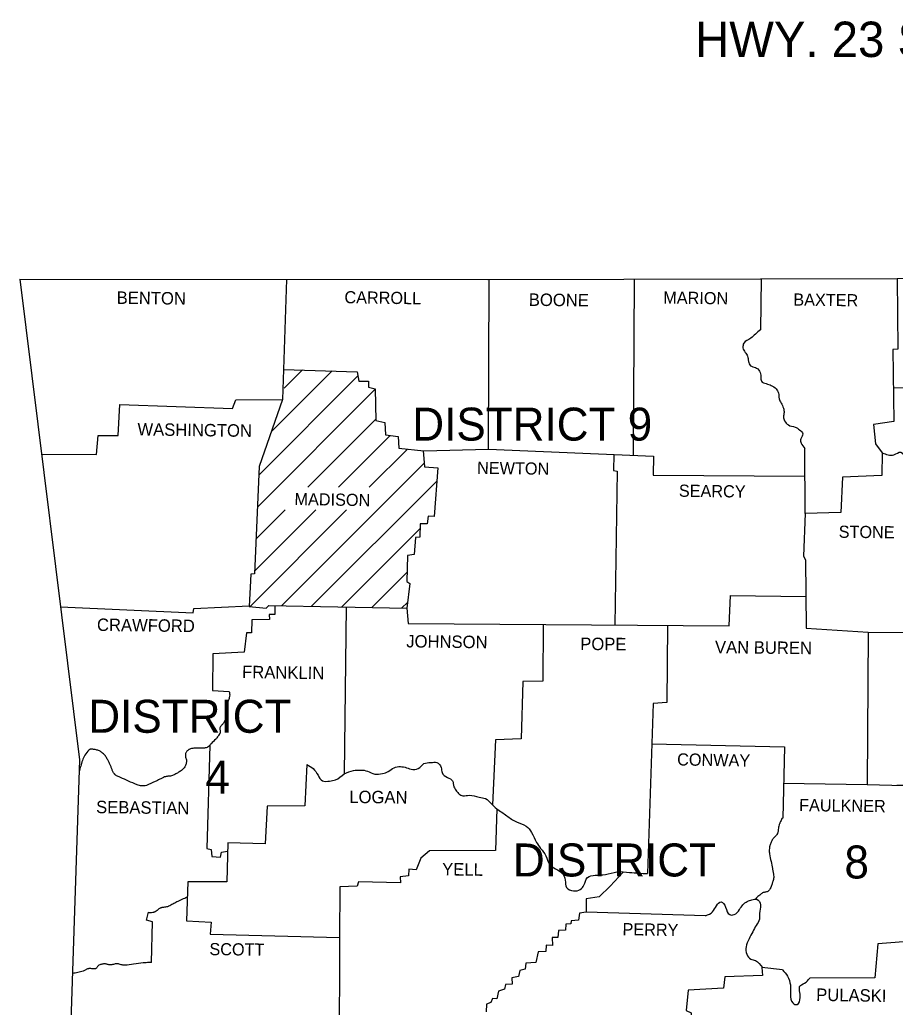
# Model space of a CAD drawing. Extents: x 0 to 3171, y 0 to 2059.
# Drawn here: x 2521.2 to 2824.1, y 1635.7 to 1977.1 of the extents above; entities that cross this region are included whole.
import ezdxf

# ---------------------------------------------------------------- set-up
doc = ezdxf.new("R2010")
doc.units = 0
doc.layers.add('Default', color=7, linetype='Continuous')
doc.layers.add('Level 1', color=7, linetype='Continuous')

msp = doc.modelspace()

# ---------------------------------------------------------------- linework, layer by layer
at = {"layer": 'Level 1'}
for p, q in [((2603.84, 1819.7), (2638.14, 1854)), ((2608.15, 1834.62), (2629.25, 1855.71)), ((2612.65, 1849.72), (2618.98, 1856.05)), ((2603.37, 1808.62), (2644.17, 1849.42)), ((2620.87, 1815.52), (2644.36, 1839.01)), ((2631.48, 1815.52), (2649.36, 1833.4)), ((2642.09, 1815.52), (2655.29, 1828.72)), ((2611.73, 1774.55), (2661.07, 1823.89)), ((2622.14, 1774.35), (2665.44, 1817.66)), ((2600.78, 1774.21), (2634.25, 1807.68)), ((2602.41, 1786.45), (2623.64, 1807.68)), ((2602.89, 1797.53), (2613.04, 1807.68)), ((2632.55, 1774.16), (2659.64, 1801.25)), ((2642.96, 1773.96), (2655.18, 1786.18)), ((2653.37, 1773.77), (2655.3, 1775.7))]:
    msp.add_line(p, q, dxfattribs=at)
for points in [[(2521.17, 1887.43), (2682.87, 1887.33), (2824.77, 1887.63), (2992.17, 1890.23), (3069.77, 1892.03)], [(2909.47, 1888.95), (2909.67, 1863.73), (2896.67, 1863.03), (2896.27, 1849.43), (2823.43, 1849.84)], [(2521.17, 1887.43), (2541.87, 1721.24), (2532.87, 1449.94)], [(2613.49, 1887.38), (2612.07, 1845.83)], [(2612.43, 1856.26), (2637.87, 1855.43), (2638.47, 1852.23), (2641.87, 1852.13), (2641.77, 1850.13), (2644.17, 1849.53), (2644.37, 1838.63), (2647.47, 1837.93), (2647.67, 1833.63), (2652.07, 1833.03), (2652.27, 1829.03), (2660.97, 1828.13), (2683.37, 1828.63), (2683.57, 1887.33)], [(2733.68, 1887.44), (2733.37, 1826.53)], [(2777.68, 1887.53), (2777.47, 1869.93)], [(2824.76, 1887.63), (2824.97, 1863.23), (2823.27, 1863.13), (2823.57, 1838.23), (2816.57, 1837.23), (2817.17, 1830.53), (2819.57, 1827.43), (2819.37, 1819.53), (2805.77, 1819.03), (2805.27, 1806.83), (2792.87, 1806.44), (2792.27, 1791.64), (2792.97, 1790.44), (2793.27, 1766.84), (2814.67, 1765.44), (2814.37, 1712.74), (2831.37, 1712.24), (2831.37, 1658.64), (2817.97, 1657.64), (2816.97, 1645.84), (2794.47, 1645.74)], [(2528.71, 1826.94), (2547.77, 1826.83), (2548.27, 1833.43), (2555.17, 1833.43), (2555.77, 1844.13), (2594.77, 1842.73), (2595.97, 1845.73), (2612.07, 1845.83), (2603.97, 1822.63), (2602.37, 1785.54), (2601.17, 1785.44), (2600.57, 1774.24), (2606.47, 1773.74), (2607.37, 1774.64), (2655.07, 1773.74), (2655.57, 1768.44)], [(2660.75, 1828.16), (2661.17, 1822.53), (2665.77, 1822.23), (2664.57, 1805.44), (2662.47, 1805.54), (2662.07, 1802.84), (2659.67, 1802.84), (2659.57, 1798.24), (2658.07, 1798.14), (2657.57, 1792.24), (2655.37, 1791.94), (2655.07, 1782.94), (2656.07, 1782.24), (2655.07, 1773.74)], [(2683.37, 1828.63), (2740.37, 1826.23), (2740.27, 1819.73), (2792.81, 1819.33)], [(2726.68, 1826.81), (2726.57, 1821.33), (2727.87, 1821.03), (2727.06, 1767.86)], [(2792.87, 1806.44), (2792.77, 1828.93)], [(2655.57, 1768.44), (2766.57, 1767.54), (2767.07, 1778.04), (2793.13, 1777.73)], [(2535.28, 1774.15), (2581.17, 1772.04), (2581.37, 1773.64), (2600.59, 1774.55)], [(2609.37, 1774.6), (2609.37, 1771.54), (2607.47, 1771.54), (2607.57, 1769.74), (2601.47, 1769.64), (2601.37, 1765.14), (2599.67, 1765.14), (2598.77, 1758.44), (2587.97, 1757.94), (2587.87, 1745.24), (2593.67, 1744.84)], [(2634.07, 1774.14), (2633.37, 1716.44)], [(2702.2, 1768.06), (2702.1, 1748.47), (2695.2, 1748.37), (2694.6, 1728.47), (2685.8, 1728.17), (2684.71, 1705.73)], [(2745.27, 1767.71), (2745.07, 1741.14), (2740.27, 1740.74), (2738.37, 1681.94)], [(2814.67, 1765.44), (2866.07, 1765.14), (2870.47, 1767.24), (2870.17, 1728.14), (2867.17, 1726.84), (2864.47, 1724.54), (2863.57, 1723.64), (2863.47, 1712.44), (2824.57, 1712.44)], [(2586.91, 1726.31), (2585.87, 1690.64), (2587.37, 1690.24), (2587.67, 1687.84), (2590.67, 1687.64), (2590.97, 1689.34), (2593.09, 1689.69)], [(2739.82, 1726.84), (2785.77, 1725.74), (2785.17, 1701.04)], [(2620.47, 1719.64), (2619.77, 1705.34), (2606.77, 1705.24), (2606.07, 1692.24), (2593.17, 1692.54), (2592.77, 1679.14), (2579.27, 1679.04), (2578.87, 1665.64), (2587.37, 1665.14), (2587.07, 1661.04), (2631.81, 1659.8)], [(2785.27, 1713.14), (2814.37, 1712.74)], [(2686.17, 1704.34), (2685.77, 1689.94), (2662.97, 1689.84), (2659.97, 1687.24), (2658.27, 1683.24), (2655.77, 1683.44), (2655.67, 1681.14), (2652.77, 1680.84), (2652.87, 1678.74), (2638.37, 1679.14), (2637.87, 1677.54), (2631.87, 1677.34), (2631.81, 1659.8)], [(2729.93, 1682.47), (2725.47, 1677.64), (2721.57, 1673.94), (2717.07, 1673.24), (2717.07, 1668.54), (2714.87, 1668.24), (2714.47, 1665.84), (2711.97, 1665.64), (2711.77, 1664.54), (2710.07, 1664.44), (2709.97, 1662.34), (2707.57, 1662.24), (2707.37, 1659.84), (2705.37, 1659.84), (2705.47, 1657.04), (2703.27, 1657.24), (2703.17, 1655.04), (2700.47, 1654.84), (2699.67, 1651.24), (2696.27, 1650.94), (2695.97, 1648.94), (2694.17, 1648.44), (2693.67, 1646.34), (2691.37, 1645.84), (2691.57, 1643.74), (2689.27, 1643.54), (2688.87, 1641.94), (2686.77, 1641.34), (2686.27, 1638.64), (2684.67, 1638.74), (2684.17, 1637.34), (2682.67, 1636.84), (2682.57, 1634.14)], [(2566.77, 1651.14), (2567.07, 1665.24), (2565.07, 1665.84), (2565.67, 1668.54)], [(2758.37, 1667.34), (2717.07, 1668.64)], [(2631.81, 1659.8), (2631.67, 1618.84), (2626.67, 1618.74), (2627.07, 1615.74), (2622.27, 1615.84), (2622.17, 1613.64), (2617.47, 1613.64), (2617.57, 1612.04), (2610.57, 1611.84), (2610.47, 1605.74), (2603.67, 1606.34), (2602.57, 1557.14), (2564.07, 1557.24), (2563.17, 1545.84), (2564.57, 1544.84), (2564.47, 1532.04), (2535.64, 1533.31)], [(2785.07, 1648.64), (2777.87, 1649.44), (2778.17, 1646.74), (2765.07, 1646.24), (2764.67, 1642.34), (2752.37, 1641.64), (2751.67, 1634.64), (2753.47, 1633.74), (2753.47, 1629.14)]]:
    msp.add_lwpolyline(points, dxfattribs=at)
for points in [[(2777.47, 1869.93), (2775.67, 1868.43), (2774.07, 1867.03), (2771.67, 1865.33), (2771.37, 1863.73), (2772.17, 1862.13), (2772.97, 1860.83), (2773.27, 1859.03), (2773.97, 1857.53), (2775.67, 1856.93), (2777.07, 1855.63), (2777.57, 1853.83), (2777.77, 1852.13), (2779.37, 1851.33), (2781.17, 1850.73), (2782.87, 1849.53), (2783.67, 1848.03), (2783.87, 1846.13), (2784.57, 1844.63), (2785.37, 1842.83), (2785.57, 1841.33), (2785.37, 1839.83), (2785.77, 1838.43), (2787.07, 1837.03), (2789.37, 1836.33), (2790.97, 1835.33), (2792.07, 1833.93), (2791.37, 1832.23), (2791.47, 1830.73), (2792.77, 1828.93)], [(2819.57, 1827.43), (2823.57, 1826.73), (2825.97, 1827.63), (2827.67, 1825.03), (2828.57, 1823.03), (2830.07, 1820.13), (2832.47, 1819.23), (2834.27, 1817.63), (2834.27, 1815.93), (2832.67, 1814.33), (2831.47, 1812.73), (2831.87, 1810.83), (2832.27, 1808.23), (2832.27, 1805.74), (2831.67, 1803.44), (2831.17, 1801.34), (2831.67, 1799.54), (2833.57, 1799.84), (2835.57, 1801.34), (2837.67, 1801.34), (2839.67, 1800.24), (2841.77, 1798.34), (2843.87, 1798.74), (2845.57, 1799.24), (2847.97, 1799.94), (2849.67, 1799.04), (2851.17, 1797.84), (2852.97, 1795.94), (2854.67, 1794.74), (2856.87, 1793.64), (2859.57, 1792.94), (2862.07, 1791.24), (2862.47, 1788.34), (2862.37, 1785.84), (2862.17, 1782.74), (2861.97, 1779.34), (2862.27, 1776.04), (2863.37, 1773.84), (2864.77, 1771.24), (2865.17, 1768.84), (2865.07, 1765.04)], [(2593.67, 1744.84), (2593.76, 1744.31), (2593.8, 1743.78), (2593.67, 1742.74), (2593.49, 1742.18), (2593.28, 1741.64), (2593.06, 1741.09), (2592.87, 1740.54), (2592.37, 1738.64), (2592.37, 1738.02), (2592.52, 1737.39), (2592.68, 1736.76), (2592.7, 1736.45), (2592.67, 1736.14), (2592.3, 1735.11), (2591.77, 1734.14), (2591.46, 1733.72), (2591.11, 1733.34), (2590.76, 1732.95), (2590.47, 1732.54), (2590.39, 1732.06), (2590.48, 1731.54), (2590.56, 1731.01), (2590.47, 1730.54), (2590.31, 1730.26), (2590.14, 1729.98), (2589.79, 1729.44), (2589.4, 1728.92), (2588.97, 1728.44), (2587.37, 1726.84), (2586.73, 1726.12), (2586.39, 1725.79), (2586.19, 1725.65), (2586.08, 1725.59), (2585.97, 1725.54), (2585.35, 1725.37), (2584.73, 1725.33), (2584.1, 1725.34), (2583.78, 1725.35), (2583.47, 1725.34), (2582.42, 1725.29), (2581.37, 1725.24), (2580.83, 1725.18), (2580.3, 1725.07), (2579.78, 1724.87), (2579.52, 1724.72), (2579.27, 1724.54), (2578.94, 1724.21), (2578.71, 1723.84), (2578.56, 1723.45), (2578.47, 1723.04), (2578.49, 1722.46), (2578.66, 1721.89), (2578.83, 1721.31), (2578.87, 1720.74), (2578.78, 1720.17), (2578.63, 1719.61), (2578.07, 1718.54), (2577.08, 1717.57), (2575.97, 1716.84), (2574.84, 1716.22), (2573.67, 1715.74), (2573.07, 1715.61), (2572.46, 1715.56), (2571.85, 1715.5), (2571.27, 1715.34), (2570.44, 1714.95), (2569.62, 1714.55), (2568.8, 1714.14), (2567.97, 1713.74), (2564.97, 1712.44), (2564.19, 1712.25), (2563.37, 1712.24), (2562.55, 1712.38), (2561.77, 1712.64), (2558.77, 1713.94), (2556.07, 1715.14), (2555.51, 1715.37), (2554.95, 1715.62), (2554.43, 1715.92), (2554.19, 1716.11), (2554.08, 1716.22), (2553.97, 1716.34), (2553.4, 1717.2), (2553.01, 1718.14), (2552.67, 1719.11), (2552.49, 1719.58), (2552.27, 1720.04), (2551.74, 1721.04), (2551.17, 1722.04), (2550.79, 1722.6), (2550.35, 1723.12), (2549.85, 1723.6), (2549.57, 1723.82), (2549.27, 1724.04), (2548.71, 1724.35), (2548.14, 1724.57), (2547.56, 1724.72), (2546.97, 1724.84), (2546.49, 1724.93), (2545.98, 1724.98), (2545.5, 1724.91), (2545.27, 1724.81), (2545.17, 1724.73), (2545.07, 1724.64), (2543.72, 1722.85), (2542.85, 1720.99), (2542.25, 1719.08), (2541.73, 1717.14)], [(2620.47, 1719.64), (2622.67, 1718.24), (2624.37, 1715.94), (2625.87, 1714.04), (2628.37, 1713.94), (2630.37, 1714.34), (2633.37, 1716.44)], [(2633.37, 1716.44), (2636.67, 1717.54), (2639.07, 1717.74), (2641.47, 1717.34), (2643.97, 1716.34), (2646.67, 1716.54), (2648.67, 1717.24), (2650.67, 1718.54), (2652.87, 1718.94), (2654.97, 1718.54), (2657.17, 1717.94), (2659.57, 1718.64), (2660.97, 1719.94), (2663.37, 1720.34), (2665.47, 1720.34), (2666.97, 1718.64), (2667.27, 1716.84), (2669.17, 1715.14), (2670.87, 1714.04), (2671.37, 1711.94), (2672.27, 1710.44), (2673.17, 1709.44), (2674.47, 1708.84), (2676.67, 1709.04), (2680.07, 1708.34), (2682.27, 1707.84), (2684.27, 1706.14), (2686.17, 1704.34)], [(2686.17, 1704.34), (2689.67, 1701.94), (2692.97, 1699.84), (2696.37, 1698.34), (2698.27, 1696.14), (2699.97, 1692.74), (2701.37, 1690.64), (2703.17, 1688.04), (2704.47, 1685.14), (2706.57, 1683.54), (2708.77, 1682.14), (2709.87, 1679.64), (2710.37, 1677.14), (2712.77, 1675.94), (2715.07, 1676.44), (2716.37, 1677.94), (2717.57, 1680.54), (2720.27, 1681.34), (2723.77, 1681.64), (2727.77, 1682.54), (2732.17, 1682.34), (2738.37, 1681.94)], [(2785.17, 1701.04), (2785.03, 1701.08), (2784.87, 1700.95), (2784.53, 1700.34), (2784.18, 1699.51), (2784.02, 1699.1), (2783.87, 1698.74), (2783.66, 1697.98), (2783.58, 1697.21), (2783.5, 1696.45), (2783.41, 1696.09), (2783.27, 1695.74), (2782.92, 1695.23), (2782.49, 1694.78), (2782.05, 1694.33), (2781.67, 1693.84), (2781.36, 1693.31), (2781.08, 1692.77), (2780.67, 1691.64), (2780.6, 1691.28), (2780.54, 1690.91), (2780.47, 1690.19), (2780.48, 1689.46), (2780.57, 1688.74), (2781.07, 1686.14), (2781.57, 1683.64), (2781.78, 1682.49), (2781.88, 1681.91), (2781.97, 1681.34), (2781.99, 1680.61), (2781.88, 1679.89), (2781.69, 1679.16), (2781.58, 1678.8), (2781.47, 1678.44), (2781.25, 1677.76), (2780.98, 1677.11), (2780.63, 1676.5), (2780.42, 1676.21), (2780.3, 1676.07), (2780.17, 1675.94), (2779.71, 1675.66), (2779.19, 1675.54), (2778.65, 1675.45), (2778.17, 1675.24), (2777.84, 1675), (2777.51, 1674.77), (2776.86, 1674.28), (2776.25, 1673.74), (2775.74, 1673.12)], [(2565.67, 1668.54), (2566.21, 1668.46), (2566.78, 1668.48), (2567.61, 1668.65), (2567.74, 1668.69), (2567.87, 1668.74), (2568.15, 1668.88), (2568.42, 1669.05), (2568.92, 1669.45), (2569.42, 1669.84), (2569.83, 1670.08), (2569.97, 1670.14), (2570.31, 1670.24), (2570.66, 1670.31), (2571.38, 1670.4), (2572.1, 1670.51), (2572.44, 1670.61), (2572.77, 1670.74), (2573.47, 1671.11), (2574.17, 1671.5), (2574.86, 1671.88), (2575.57, 1672.24), (2579.12, 1673.86)], [(2758.37, 1667.34), (2760.87, 1668.74), (2762.17, 1670.84), (2763.77, 1672.14), (2765.37, 1670.34), (2766.77, 1667.74), (2768.27, 1667.74), (2770.17, 1669.54), (2771.37, 1671.14), (2772.87, 1672.34), (2774.47, 1672.84), (2776.17, 1673.04), (2777.47, 1671.14), (2777.07, 1668.14), (2777.07, 1666.14), (2775.97, 1664.04), (2774.77, 1661.84), (2773.47, 1659.34), (2772.47, 1656.64), (2772.67, 1654.04), (2774.07, 1652.34), (2775.67, 1651.84), (2778.09, 1649.41)], [(2566.77, 1651.14), (2566.05, 1651.15), (2565.32, 1651.14), (2563.87, 1651.04), (2560.57, 1650.64), (2557.57, 1650.24), (2557.23, 1650.23), (2556.89, 1650.27), (2556.22, 1650.44), (2555.55, 1650.63), (2555.04, 1650.73), (2554.87, 1650.74), (2554.24, 1650.69), (2553.62, 1650.55), (2552.99, 1650.4), (2552.37, 1650.34), (2551.94, 1650.4), (2551.52, 1650.54), (2551.1, 1650.67), (2550.67, 1650.74), (2550.15, 1650.71), (2549.62, 1650.61), (2549.1, 1650.45), (2548.57, 1650.24), (2548.22, 1649.98), (2547.96, 1649.62), (2547.7, 1649.27), (2547.37, 1649.04), (2547.07, 1648.97), (2546.76, 1648.96), (2546.12, 1649.04), (2545.48, 1649.11), (2545.02, 1649.08), (2544.87, 1649.04), (2544.42, 1648.85), (2543.98, 1648.63), (2543.53, 1648.41), (2543.07, 1648.24), (2542.17, 1647.98), (2541.26, 1647.74), (2540.34, 1647.56), (2539.42, 1647.42)], [(2785.07, 1648.64), (2786.77, 1646.44), (2787.77, 1643.44), (2787.77, 1640.04), (2788.57, 1637.24), (2790.17, 1636.64), (2791.17, 1639.04), (2790.97, 1641.44), (2790.97, 1642.84), (2792.67, 1644.04), (2794.47, 1645.74)]]:
    msp.add_spline(points, degree=3, dxfattribs=at)

# ---------------------------------------------------------------- texts
at = {"layer": 'Default'}
msp.add_text('MADISON', height=4.201, rotation=359.0906, dxfattribs=at).set_placement((2616.19, 1809.36))
at = {"layer": 'Level 1'}
for s, height, p in [('HWY. 23 STRS. & APPRS. (MADISON CO.) (S)', 12.2398, (2754.8, 1964.25)), ('DISTRICT 9', 11.4, (2656.97, 1831.63)), ('DISTRICT', 11.4, (2544.88, 1730.62)), ('4', 11.4, (2585.38, 1709.62)), ('DISTRICT', 11.4, (2691.77, 1680.94)), ('8', 11.4, (2806.47, 1680.24))]:
    msp.add_text(s, height=height, dxfattribs=at).set_placement(p)
for s, height, rotation, p in [('BENTON', 4.301, 359.2527, (2554.67, 1878.93)), ('CARROLL', 4.2, 359.1481, (2633.47, 1879.13)), ('BOONE', 4.301, 359.4001, (2697.27, 1878.23)), ('MARION', 4.2, 359.1854, (2743.77, 1879.03)), ('BAXTER', 4.2, 359.256, (2788.77, 1878.33)), ('WASHINGTON', 4.299, 359.232, (2561.87, 1833.43)), ('NEWTON', 4.2, 359.2717, (2679.37, 1820.13)), ('SEARCY', 4.199, 359.2527, (2749.17, 1812.23)), ('STONE', 4.199, 359.4001, (2804.47, 1798.04)), ('CRAWFORD', 4.299, 359.2771, (2547.87, 1765.84)), ('JOHNSON', 4.301, 359.3514, (2654.87, 1760.14)), ('POPE', 4.301, 359.6155, (2715.07, 1759.24)), ('VAN BUREN', 4.301, 359.3508, (2761.67, 1758.14)), ('FRANKLIN', 4.301, 359.1816, (2598.07, 1749.54)), ('CONWAY', 4.199, 359.0372, (2748.57, 1719.34)), ('LOGAN', 4.301, 359.3969, (2635.17, 1706.34)), ('SEBASTIAN', 4.299, 359.2816, (2547.57, 1702.84)), ('FAULKNER', 4.2, 359.2486, (2790.77, 1703.54)), ('YELL', 4.301, 359.1987, (2667.27, 1681.34)), ('PERRY', 4.2, 359.0858, (2729.67, 1660.64)), ('SCOTT', 4.2, 359.4063, (2586.77, 1653.74)), ('PULASKI', 4.301, 359.0531, (2796.67, 1637.94))]:
    msp.add_text(s, height=height, rotation=rotation, dxfattribs=at).set_placement(p)

doc.saveas('drawing.dxf')
